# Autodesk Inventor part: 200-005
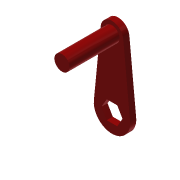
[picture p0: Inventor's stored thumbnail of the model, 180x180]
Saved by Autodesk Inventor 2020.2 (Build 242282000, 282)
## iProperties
Created: 2014-01
Part Number: 200-005
Material: Ogólny
Document SubType Name: Modeling
Designer: F.Stasiak
Density: 1 g/cm^3
Appearance: Czerwona
Manager: www.cadconsulting.pl
Company: Fabian Stasiak CAD Consulting
Author: F.Stasiak
Subject: Zbiór ćwiczeń. Autodesk Inventor 2020. Kurs podstawowy
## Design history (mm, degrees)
sketch "Szkic1"
  geometry: L1 (-3.464, -6)-(-6.928, 0); L2 (-6.928, 0)-(-3.464, 6); L3 (-3.464, 6)-(3.464, 6); L4 (3.464, 6)-(6.928, 0); L5 (6.928, 0)-(3.464, -6); L6 (3.464, -6)-(-3.464, -6); L7 (0, 45)-(0, 0); L8 (7.462, 45.75)-(11.94, 1.2); L9 (-7.462, 45.75)-(-11.94, 1.2); C1 r 5 at (0, 45); A1 r 12 centre (0, 0) between (11.94, 1.2) and (-11.94, 1.2); A2 r 7.5 centre (0, 45) between (7.462, 45.75) and (-7.462, 45.75); 2 further points
  constraints: 18 end point, 4 point on circle, 4 tangent, 3 centre point, 3 coincident, 1 perpendicular, 1 vertical, 13 other
  dimensions: "d0" = 12 distance between parallel lines of L6 L3; "d1" = 24 diameter of A1; "d2" = 15 diameter of A2; "d3" = 45 distance of L7.start L7.end; "d4" = 10 diameter of C1
extrude "Wyciągnięcie proste1" new body sketch "Szkic1" stored distance "d5" = 4; taper "d6" = 0 deg
extrude "Wyciągnięcie proste2" join sketch "Szkic1" distance "d7" = 35; taper "d8" = 0 deg
node "Bryła1"
